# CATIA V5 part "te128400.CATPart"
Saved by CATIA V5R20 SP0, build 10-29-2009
Part number: 1
Definition: NONE
Nomenclature: 1
Source: Unknown
Description: PART-1-DESC
Bounding box of the stored display mesh (mm): x 0 to 400, y -6 to 6, z -5.85 to 5.85
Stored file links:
  C:\Users\Utente\Desktop\IO LAVORO\3D X SITO CF\CUMSA\3D files TE\te128400.CATPart
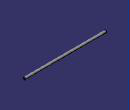
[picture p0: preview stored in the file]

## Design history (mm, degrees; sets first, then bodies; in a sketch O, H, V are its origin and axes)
Body1 "1" (main body)
  Solid1: solid without history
